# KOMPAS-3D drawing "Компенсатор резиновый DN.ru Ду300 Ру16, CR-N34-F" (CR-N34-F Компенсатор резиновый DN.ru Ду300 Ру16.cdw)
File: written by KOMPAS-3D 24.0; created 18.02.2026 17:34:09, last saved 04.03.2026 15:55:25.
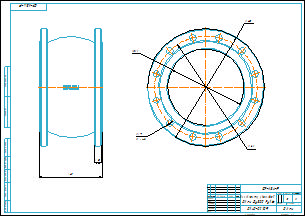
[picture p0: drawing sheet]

Document properties: Типовые: Типовые; Автор: DN.RU; Форматы листов документа: A2; Полное имя файла: CR-N34-F Компенсатор резиновый DN.ru Ду300 Ру16.m3d; Масса: 30; Наименование: Компенсатор резиновый DN.ru Ду300 Ру16; Количество листов документа: 1; Комментарий: D140-02109; Примечание: D140-02109

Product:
- Body: Твердое тело2  | qty 1
    Масса: 101.598119
- Part/product: Компенсатор резиновый DN.ru Ду300 Ру16  | designation CR-N34-F
    Масса: 30
    Раздел спецификации: Прочие изделия
    Комментарий: D140-02109
    Примечание: D140-02109
    additional columns: Типовые

Views: Вид 1, Спереди, Проекционный вид 2
Referenced files in E:\Работа\Зайцев\CR-N34-F Компенсатор резиновый DN.ru ДУ25-300 Ру10-16\DN300_PN16\: CR-N34-F Компенсатор резиновый DN.ru Ду300 Ру16.m3d
Referenced files in E:\Работа\Зайцев\Для компаса\: чертеж DN.ru А3.cdt
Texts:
  CR-N34-F
  чертеж DN.ru А3.cdt
  Компенсатор резиновый
  DN.ru Ду300 Ру16
  Твердое тело2
  Компенсатор резиновый DN.ru Ду300 Ру16
  CR-N34-F Компенсатор резиновый DN.ru Ду300 Ру16
Dimensions and other numbers on the sheet: 0; 3; 2; 4; 245; 26; 460; 400; 300; 27; 12 отв.; 1:2; 1; 30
